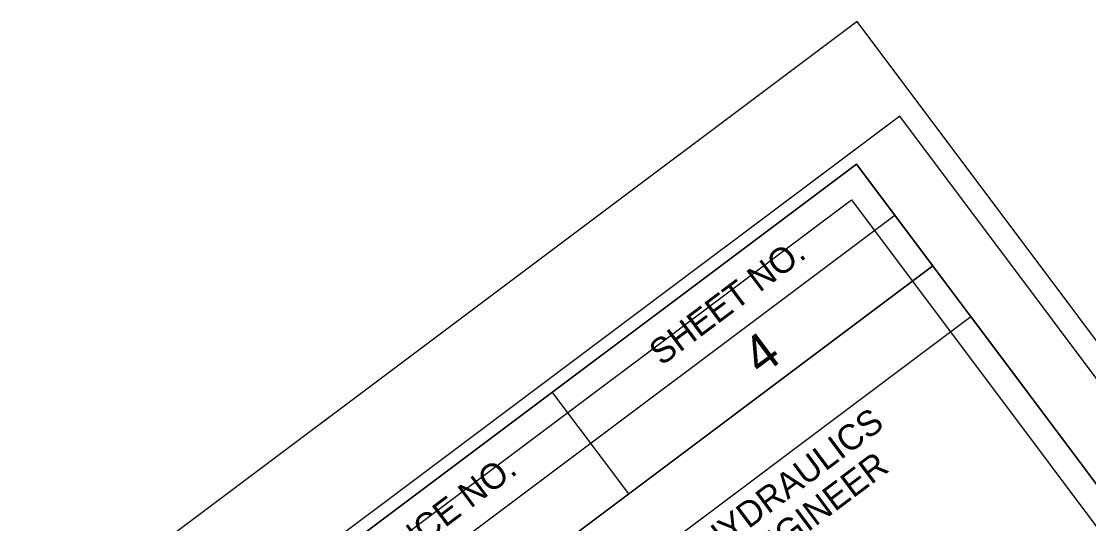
# Model space of a CAD drawing. Extents: x 2186558 to 2188589, y 629855 to 631741.
# Drawn here: x 2187767.1 to 2187977.7, y 631641.9 to 631741 of the extents above; entities that cross this region are included whole.
import ezdxf

# ---------------------------------------------------------------- set-up
doc = ezdxf.new("R2010")
doc.units = 0
for name, color, linetype in [('Scratch_Level_8', 7, 'Continuous'), ('Sheet Cutting Line CELL', 7, 'Continuous'), ('Sheet Data Field CELL', 7, 'Continuous'), ('Sheet Plan CELL', 7, 'Continuous'), ('Sheet Plan Layout CELL', 7, 'Continuous'), ('Sheet Plot Border Inside CELL', 7, 'Continuous'), ('Sheet Plot Border Outside CELL', 7, 'Continuous')]:
    doc.layers.add(name, color=color, linetype=linetype)

msp = doc.modelspace()

# ---------------------------------------------------------------- linework, layer by layer
at = {"layer": 'Scratch_Level_8'}
msp.add_lwpolyline([(2186738.7, 630811.99), (2187930.9, 631705.79), (2188554.73, 630873.69), (2187362.53, 629979.89)], close=True, dxfattribs=at)
at = {"layer": 'Sheet Cutting Line CELL'}
msp.add_line((2187932, 631741), (2186585.01, 630731.15), dxfattribs=at)
at = {"layer": 'Sheet Plan CELL'}
for p, q in [((2187779.33, 631582.77), (2187939.4, 631702.76)), ((2187786.86, 631572.75), (2187946.9, 631692.76)), ((2187786.86, 631572.75), (2187946.9, 631692.76)), ((2187871.88, 631667.75), (2187886.92, 631647.78))]:
    msp.add_line(p, q, dxfattribs=at)
for points in [[(2187931.9, 631712.82), (2186731.71, 630813.02), (2187361.55, 629972.91), (2188561.73, 630872.69)], [(2187771.81, 631592.82), (2187931.9, 631712.82), (2187946.9, 631692.76), (2187786.86, 631572.75)], [(2187874.4, 631622.77), (2187954.4, 631682.76), (2188021.9, 631592.74), (2187941.9, 631532.75)]]:
    msp.add_lwpolyline(points, close=True, dxfattribs=at)
at = {"layer": 'Sheet Plan Layout CELL'}
msp.add_lwpolyline([(2187867.31, 631400.07), (2188058.75, 631543.6), (2187931.91, 631712.83), (2187740.45, 631569.29)], close=True, dxfattribs=at)
at = {"layer": 'Sheet Plot Border Inside CELL'}
msp.add_lwpolyline([(2187240.25, 629878.83), (2188573.22, 630878.18), (2187940.39, 631722.3), (2186607.41, 630722.95)], close=True, dxfattribs=at)
at = {"layer": 'Sheet Plot Border Outside CELL'}
msp.add_lwpolyline([(2187241.85, 629855.03), (2188588.83, 630864.88), (2187932, 631741), (2186585.01, 630731.15)], close=True, dxfattribs=at)

# ---------------------------------------------------------------- texts
at = {"layer": 'Sheet Data Field CELL'}
msp.add_text('4', height=7.5, rotation=36.8593, dxfattribs=at).set_placement((2187913.04, 631670.87))
at = {"layer": 'Sheet Plan CELL'}
for s, height, p in [('SHEET NO.', 5, (2187893.42, 631672.94)), ('HYDRAULICS', 5, (2187903.14, 631635.22)), ('ENGINEER', 5, (2187910.66, 631631.47)), ('PROJECT REFERENCE NO.', 5.0001, (2187794.81, 631599.15))]:
    msp.add_text(s, height=height, rotation=36.8593, dxfattribs=at).set_placement(p)

doc.saveas('drawing.dxf')
